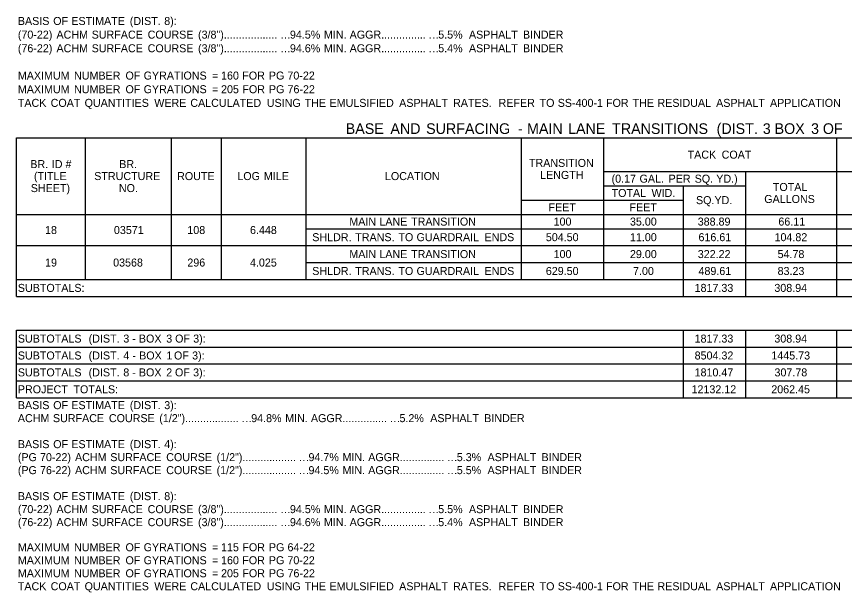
# Model space of a CAD drawing. Extents: x 540541 to 1930787, y -1948574 to 596640.
# Drawn here: x 554022 to 554642, y -1946967 to -1946535 of the extents above; entities that cross this region are included whole.
import ezdxf

# ---------------------------------------------------------------- set-up
doc = ezdxf.new("R2010")
doc.units = 0
doc.layers.add('Default', color=7, linetype='Continuous')

msp = doc.modelspace()

# ---------------------------------------------------------------- linework, layer by layer
at = {"layer": 'Default'}
for p, q in [((554021.75, -1946626.07), (554900.22, -1946626.07)), ((554021.75, -1946745.02), (554021.75, -1946626.07)), ((554073.42, -1946732.34), (554073.42, -1946626.07)), ((554137.77, -1946732.34), (554137.77, -1946626.07)), ((554175.31, -1946732.34), (554175.31, -1946626.07)), ((554238.69, -1946732.34), (554238.69, -1946626.07)), ((554400.05, -1946732.34), (554400.05, -1946626.07)), ((554461.96, -1946732.34), (554461.96, -1946626.07)), ((554636.49, -1946745.02), (554636.49, -1946626.07)), ((554461.96, -1946651.42), (554900.22, -1946651.42)), ((554568.24, -1946662.14), (554568.24, -1946651.42)), ((554568.24, -1946745.02), (554568.24, -1946651.42)), ((554461.96, -1946662.14), (554568.24, -1946662.14)), ((554521.44, -1946745.02), (554521.44, -1946662.14)), ((554400.05, -1946672.87), (554521.44, -1946672.87)), ((554521.44, -1946694.32), (554521.44, -1946672.87)), ((554021.75, -1946683.59), (554900.22, -1946683.59)), ((554521.44, -1946683.59), (554900.22, -1946683.59)), ((554238.69, -1946694.32), (554900.22, -1946694.32)), ((554238.69, -1946694.32), (554900.22, -1946694.32)), ((554021.75, -1946706.99), (554900.22, -1946706.99)), ((554238.69, -1946706.99), (554900.22, -1946706.99)), ((554238.69, -1946719.67), (554900.22, -1946719.67)), ((554238.69, -1946719.67), (554900.22, -1946719.67)), ((554021.75, -1946732.34), (554521.44, -1946732.34)), ((554238.69, -1946732.34), (554400.05, -1946732.34)), ((554400.05, -1946732.34), (554900.22, -1946732.34)), ((554021.75, -1946745.02), (554900.22, -1946745.02)), ((554021.75, -1946770.37), (554900.22, -1946770.37)), ((554021.75, -1946770.37), (554900.22, -1946770.37)), ((554021.75, -1946821.07), (554021.75, -1946770.37)), ((554521.44, -1946821.07), (554521.44, -1946770.37)), ((554568.24, -1946821.07), (554568.24, -1946770.37)), ((554636.49, -1946821.07), (554636.49, -1946770.37)), ((554021.75, -1946783.04), (554900.22, -1946783.04)), ((554021.75, -1946795.72), (554900.22, -1946795.72)), ((554021.75, -1946808.39), (554900.22, -1946808.39)), ((554021.75, -1946821.07), (554900.22, -1946821.07))]:
    msp.add_line(p, q, dxfattribs=at)

# ---------------------------------------------------------------- texts
for s, height, p in [('BASIS', 6, (554022.72, -1946541.5)), (' OF', 6, (554046.99, -1946541.5)), (' ESTIMATE', 6, (554060.57, -1946541.5)), (' (DIST.', 6, (554104.38, -1946541.5)), (' 8):', 6, (554130.19, -1946541.5)), ('(70-22)', 6, (554022.72, -1946551.74)), (' ACHM', 6, (554049.43, -1946551.74)), (' SURFACE', 6, (554075.81, -1946551.74)), (' COURSE', 6, (554117.76, -1946551.74)), (' (3/8")..................', 6, (554155.51, -1946551.74)), ('94.5%', 6, (554226.61, -1946551.74)), (' MIN.', 6, (554249.85, -1946551.74)), (' AGGR...............', 6, (554269.14, -1946551.74)), ('5.5%', 6, (554337.74, -1946551.74)), ('  ASPHALT', 6, (554356.32, -1946551.74)), (' BINDER', 6, (554399.02, -1946551.74)), ('(76-22)', 6, (554022.72, -1946561.98)), (' (3/8")..................', 6, (554155.51, -1946561.98)), ('…', 6, (554219.21, -1946551.74)), ('…', 6, (554330.34, -1946551.74)), (' ACHM', 6, (554049.43, -1946561.98)), (' SURFACE', 6, (554075.81, -1946561.98)), (' COURSE', 6, (554117.76, -1946561.98)), ('…', 6, (554219.21, -1946561.98)), ('94.6%', 6, (554226.61, -1946561.98)), (' MIN.', 6, (554249.85, -1946561.98)), (' AGGR...............', 6, (554269.14, -1946561.98)), ('…', 6, (554330.34, -1946561.98)), ('5.4%', 6, (554337.74, -1946561.98)), ('  ASPHALT', 6, (554356.32, -1946561.98)), (' BINDER', 6, (554399.02, -1946561.98)), ('MAXIMUM', 6, (554022.72, -1946582.45)), (' NUMBER', 6, (554062.61, -1946582.45)), (' OF', 6, (554101.16, -1946582.45)), (' GYRATIONS', 6, (554114.75, -1946582.45)), (' =', 6, (554166.02, -1946582.45)), (' 160', 6, (554172.77, -1946582.45)), (' FOR', 6, (554188.68, -1946582.45)), (' PG', 6, (554208.59, -1946582.45)), (' 70-22', 6, (554222.5, -1946582.45)), ('MAXIMUM', 6, (554022.72, -1946592.69)), (' NUMBER', 6, (554062.61, -1946592.69)), (' OF', 6, (554101.16, -1946592.69)), (' GYRATIONS', 6, (554114.75, -1946592.69)), (' 205', 6, (554172.77, -1946592.69)), (' FOR', 6, (554188.74, -1946592.69)), (' PG', 6, (554208.66, -1946592.69)), (' 76-22', 6, (554222.57, -1946592.69)), (' =', 6, (554166.02, -1946592.69)), ('TACK', 6, (554022.72, -1946602.93)), (' COAT', 6, (554045.07, -1946602.93)), (' QUANTITIES', 6, (554070.52, -1946602.93)), (' WERE', 6, (554122.72, -1946602.93)), (' CALCULATED', 6, (554149.75, -1946602.93)), (' USING', 6, (554207.07, -1946602.93)), (' THE', 6, (554235.42, -1946602.93)), (' EMULSIFIED', 6, (554254.07, -1946602.93)), (' ASPHALT', 6, (554306.26, -1946602.93)), (' RATES.', 6, (554346.63, -1946602.93)), ('  REFER', 6, (554378.51, -1946602.93)), (' TO', 6, (554411.47, -1946602.93)), (' SS-400-1', 6, (554425.06, -1946602.93)), (' FOR', 6, (554461.26, -1946602.93)), (' THE', 6, (554481.17, -1946602.93)), (' RESIDUAL', 6, (554499.82, -1946602.93)), (' ASPHALT', 6, (554543.78, -1946602.93)), (' APPLICATION', 6, (554584.15, -1946602.93)), ('BASE', 8, (554268.41, -1946623.24)), (' AND', 8, (554298.92, -1946623.24)), (' SURFACING', 8, (554325.69, -1946623.24)), (' MAIN', 8, (554401.31, -1946623.24)), (' LANE', 8, (554432.08, -1946623.24)), (' TRANSITIONS', 8, (554465.06, -1946623.24)), (' (DIST.', 8, (554543.38, -1946623.24)), (' 3', 8, (554578.01, -1946623.24)), (' BOX', 8, (554586.84, -1946623.24)), (' 3', 8, (554614.16, -1946623.24)), (' OF', 8, (554622.99, -1946623.24)), (' -', 8, (554394.57, -1946623.24)), ('TACK', 6, (554524.63, -1946641.74)), (' COAT', 6, (554547.91, -1946641.74)), ('TRANSITION', 6, (554405.73, -1946647.97)), ('BR.', 6, (554032.06, -1946648.83)), (' ID', 6, (554045.92, -1946648.83)), (' #', 6, (554056.22, -1946648.83)), ('BR.', 6, (554098.67, -1946648.83)), ('(TITLE', 6, (554034.76, -1946657.83)), ('STRUCTURE', 6, (554079.96, -1946657.83)), ('ROUTE', 6, (554142.08, -1946657.83)), ('LOG', 6, (554187.2, -1946657.83)), (' MILE', 6, (554204.86, -1946657.83)), ('LOCATION', 6, (554297.82, -1946657.83)), ('LENGTH', 6, (554414.09, -1946656.97)), ('(0.17', 6, (554467.66, -1946659.78)), (' GAL.', 6, (554486.38, -1946659.78)), (' PER', 6, (554508.16, -1946659.78)), (' SQ.', 6, (554527.69, -1946659.78)), (' YD.)', 6, (554543.88, -1946659.78)), ('SHEET)', 6, (554032.43, -1946666.83)), ('NO.', 6, (554098.44, -1946666.83)), ('TOTAL', 6, (554588.52, -1946666)), ('TOTAL', 6, (554467.67, -1946670.5)), (' WID.', 6, (554495.36, -1946670.5)), ('SQ.YD.', 6, (554530.92, -1946675.87)), ('GALLONS', 6, (554582.07, -1946675)), ('FEET', 6, (554420.38, -1946681.23)), ('FEET', 6, (554481.07, -1946681.23)), ('MAIN', 6, (554271.14, -1946691.95)), (' LANE', 6, (554291.41, -1946691.95)), (' TRANSITION', 6, (554315.19, -1946691.95)), ('100', 6, (554424.22, -1946691.95)), ('35.00', 6, (554481.42, -1946691.95)), ('388.89', 6, (554532.21, -1946691.95)), ('66.11', 6, (554592.65, -1946691.95)), ('18', 6, (554043.11, -1946698.29)), ('03571', 6, (554094.72, -1946698.29)), ('108', 6, (554149.74, -1946698.29)), ('6.448', 6, (554196.7, -1946698.29)), ('SHLDR.', 6, (554243.33, -1946703.65)), (' TRANS.', 6, (554273.34, -1946703.65)), (' TO', 6, (554305.68, -1946703.65)), (' GUARDRAIL', 6, (554319.28, -1946703.65)), (' ENDS', 6, (554370.22, -1946703.65)), ('504.50', 6, (554418.39, -1946703.65)), ('11.00', 6, (554481.42, -1946703.65)), ('616.61', 6, (554532.79, -1946703.65)), ('104.82', 6, (554589.77, -1946703.65)), ('MAIN', 6, (554271.14, -1946716.33)), (' LANE', 6, (554291.41, -1946716.33)), (' TRANSITION', 6, (554315.19, -1946716.33)), ('100', 6, (554424.22, -1946716.33)), ('29.00', 6, (554481.42, -1946716.33)), ('322.22', 6, (554532.25, -1946716.33)), ('54.78', 6, (554592.06, -1946716.33)), ('19', 6, (554043.11, -1946722.67)), ('03568', 6, (554094.13, -1946722.67)), ('296', 6, (554149.74, -1946722.67)), ('4.025', 6, (554196.68, -1946722.67)), ('SHLDR.', 6, (554243.33, -1946729)), (' TRANS.', 6, (554273.34, -1946729)), (' TO', 6, (554305.68, -1946729)), (' GUARDRAIL', 6, (554319.28, -1946729)), (' ENDS', 6, (554370.22, -1946729)), ('629.50', 6, (554418.39, -1946729)), ('7.00', 6, (554483.75, -1946729)), ('489.61', 6, (554532.79, -1946729)), ('83.23', 6, (554592.07, -1946729)), ('SUBTOTALS:', 6, (554022.72, -1946741.68)), ('1817.33', 6, (554529.87, -1946741.68)), ('308.94', 6, (554589.64, -1946741.68)), ('SUBTOTALS', 6, (554022.72, -1946779.7)), (' (DIST.', 6, (554073.55, -1946779.7)), (' 3', 6, (554099.52, -1946779.7)), (' -', 6, (554106.14, -1946779.7)), (' BOX', 6, (554111.2, -1946779.7)), (' 3', 6, (554131.69, -1946779.7)), (' OF', 6, (554138.32, -1946779.7)), (' 3):', 6, (554151.9, -1946779.7)), ('1817.33', 6, (554529.87, -1946779.7)), ('308.94', 6, (554589.64, -1946779.7)), ('SUBTOTALS', 6, (554022.72, -1946792.38)), (' (DIST.', 6, (554073.55, -1946792.38)), (' 4', 6, (554099.52, -1946792.38)), (' -', 6, (554106.31, -1946792.38)), (' BOX', 6, (554111.37, -1946792.38)), (' 1', 6, (554131.86, -1946792.38)), (' OF', 6, (554137.49, -1946792.38)), (' 3):', 6, (554151.07, -1946792.38)), ('8504.32', 6, (554529.9, -1946792.38)), ('1445.73', 6, (554587.4, -1946792.38)), ('SUBTOTALS', 6, (554022.72, -1946805.05)), (' (DIST.', 6, (554073.55, -1946805.05)), (' 8', 6, (554099.52, -1946805.05)), (' -', 6, (554106.13, -1946805.05)), (' BOX', 6, (554111.19, -1946805.05)), (' 2', 6, (554131.68, -1946805.05)), (' OF', 6, (554138.24, -1946805.05)), (' 3):', 6, (554151.83, -1946805.05)), ('1810.47', 6, (554529.88, -1946805.05)), ('307.78', 6, (554589.74, -1946805.05)), ('PROJECT', 6, (554022.72, -1946817.73)), (' TOTALS:', 6, (554062.15, -1946817.73)), ('12132.12', 6, (554527.57, -1946817.73)), ('2062.45', 6, (554587.34, -1946817.73)), ('BASIS', 6, (554022.72, -1946829.62)), (' OF', 6, (554046.99, -1946829.62)), (' ESTIMATE', 6, (554060.57, -1946829.62)), (' (DIST.', 6, (554104.38, -1946829.62)), (' 3):', 6, (554130.19, -1946829.62)), ('ACHM', 6, (554022.72, -1946839.37)), (' SURFACE', 6, (554046.78, -1946839.37)), (' COURSE', 6, (554088.72, -1946839.37)), (' (1/2")..................', 6, (554126.48, -1946839.37)), ('94.8%', 6, (554197.58, -1946839.37)), (' MIN.', 6, (554220.82, -1946839.37)), (' AGGR...............', 6, (554240.11, -1946839.37)), ('5.2%', 6, (554308.71, -1946839.37)), ('  ASPHALT', 6, (554327.29, -1946839.37)), (' BINDER', 6, (554369.98, -1946839.37)), ('…', 6, (554190.18, -1946839.37)), ('…', 6, (554301.31, -1946839.37)), ('BASIS', 6, (554022.72, -1946858.87)), (' OF', 6, (554046.99, -1946858.87)), (' ESTIMATE', 6, (554060.57, -1946858.87)), (' (DIST.', 6, (554104.38, -1946858.87)), (' 4):', 6, (554130.19, -1946858.87)), ('(PG', 6, (554022.72, -1946868.62)), (' 70-22)', 6, (554037.1, -1946868.62)), (' ACHM', 6, (554063.35, -1946868.62)), (' SURFACE', 6, (554089.73, -1946868.62)), (' COURSE', 6, (554131.68, -1946868.62)), (' (1/2")..................', 6, (554169.43, -1946868.62)), ('94.7%', 6, (554240.53, -1946868.62)), (' MIN.', 6, (554263.77, -1946868.62)), (' AGGR...............', 6, (554283.06, -1946868.62)), ('5.3%', 6, (554351.66, -1946868.62)), ('  ASPHALT', 6, (554370.24, -1946868.62)), (' BINDER', 6, (554412.94, -1946868.62)), ('(PG', 6, (554022.72, -1946878.37)), (' 76-22)', 6, (554037.1, -1946878.37)), (' (1/2")..................', 6, (554169.43, -1946878.37)), ('…', 6, (554233.13, -1946868.62)), ('…', 6, (554344.26, -1946868.62)), (' ACHM', 6, (554063.35, -1946878.37)), (' SURFACE', 6, (554089.73, -1946878.37)), (' COURSE', 6, (554131.68, -1946878.37)), ('…', 6, (554233.13, -1946878.37)), ('94.5%', 6, (554240.53, -1946878.37)), (' MIN.', 6, (554263.77, -1946878.37)), (' AGGR...............', 6, (554283.06, -1946878.37)), ('…', 6, (554344.26, -1946878.37)), ('5.5%', 6, (554351.66, -1946878.37)), ('  ASPHALT', 6, (554370.24, -1946878.37)), (' BINDER', 6, (554412.94, -1946878.37)), ('BASIS', 6, (554022.72, -1946897.87)), (' OF', 6, (554046.99, -1946897.87)), (' ESTIMATE', 6, (554060.57, -1946897.87)), (' (DIST.', 6, (554104.38, -1946897.87)), (' 8):', 6, (554130.19, -1946897.87)), ('(70-22)', 6, (554022.72, -1946907.62)), (' ACHM', 6, (554049.43, -1946907.62)), (' SURFACE', 6, (554075.81, -1946907.62)), (' COURSE', 6, (554117.76, -1946907.62)), (' (3/8")..................', 6, (554155.51, -1946907.62)), ('94.5%', 6, (554226.61, -1946907.62)), (' MIN.', 6, (554249.85, -1946907.62)), (' AGGR...............', 6, (554269.14, -1946907.62)), ('5.5%', 6, (554337.74, -1946907.62)), ('  ASPHALT', 6, (554356.32, -1946907.62)), (' BINDER', 6, (554399.02, -1946907.62)), ('…', 6, (554219.21, -1946907.62)), ('…', 6, (554330.34, -1946907.62)), ('(76-22)', 6, (554022.72, -1946917.37)), (' ACHM', 6, (554049.43, -1946917.37)), (' SURFACE', 6, (554075.81, -1946917.37)), (' COURSE', 6, (554117.76, -1946917.37)), (' (3/8")..................', 6, (554155.51, -1946917.37)), ('94.6%', 6, (554226.61, -1946917.37)), (' MIN.', 6, (554249.85, -1946917.37)), (' AGGR...............', 6, (554269.14, -1946917.37)), ('5.4%', 6, (554337.74, -1946917.37)), ('  ASPHALT', 6, (554356.32, -1946917.37)), (' BINDER', 6, (554399.02, -1946917.37)), ('…', 6, (554219.21, -1946917.37)), ('…', 6, (554330.34, -1946917.37)), ('MAXIMUM', 6, (554022.72, -1946936.19)), (' NUMBER', 6, (554062.61, -1946936.19)), (' OF', 6, (554101.16, -1946936.19)), (' GYRATIONS', 6, (554114.75, -1946936.19)), (' =', 6, (554166.02, -1946936.19)), (' 115', 6, (554172.77, -1946936.19)), (' FOR', 6, (554188.74, -1946936.19)), (' PG', 6, (554208.66, -1946936.19)), (' 64-22', 6, (554222.57, -1946936.19)), ('MAXIMUM', 6, (554022.72, -1946945.94)), (' NUMBER', 6, (554062.61, -1946945.94)), (' OF', 6, (554101.16, -1946945.94)), (' GYRATIONS', 6, (554114.75, -1946945.94)), (' 160', 6, (554172.77, -1946945.94)), (' FOR', 6, (554188.68, -1946945.94)), (' PG', 6, (554208.59, -1946945.94)), (' 70-22', 6, (554222.5, -1946945.94)), (' =', 6, (554166.02, -1946945.94)), ('MAXIMUM', 6, (554022.72, -1946955.69)), (' NUMBER', 6, (554062.61, -1946955.69)), (' OF', 6, (554101.16, -1946955.69)), (' GYRATIONS', 6, (554114.75, -1946955.69)), (' =', 6, (554166.02, -1946955.69)), (' 205', 6, (554172.77, -1946955.69)), (' FOR', 6, (554188.74, -1946955.69)), (' PG', 6, (554208.66, -1946955.69)), (' 76-22', 6, (554222.57, -1946955.69)), ('TACK', 6, (554022.72, -1946965.44)), (' COAT', 6, (554045.07, -1946965.44)), (' QUANTITIES', 6, (554070.52, -1946965.44)), (' WERE', 6, (554122.72, -1946965.44)), (' CALCULATED', 6, (554149.75, -1946965.44)), (' USING', 6, (554207.07, -1946965.44)), (' THE', 6, (554235.42, -1946965.44)), (' EMULSIFIED', 6, (554254.07, -1946965.44)), (' ASPHALT', 6, (554306.26, -1946965.44)), (' RATES.', 6, (554346.63, -1946965.44)), ('  REFER', 6, (554378.51, -1946965.44)), (' TO', 6, (554411.47, -1946965.44)), (' SS-400-1', 6, (554425.06, -1946965.44)), (' FOR', 6, (554461.26, -1946965.44)), (' THE', 6, (554481.17, -1946965.44)), (' RESIDUAL', 6, (554499.82, -1946965.44)), (' ASPHALT', 6, (554543.78, -1946965.44)), (' APPLICATION', 6, (554584.15, -1946965.44))]:
    msp.add_text(s, height=height, dxfattribs=at).set_placement(p)

doc.saveas('drawing.dxf')
